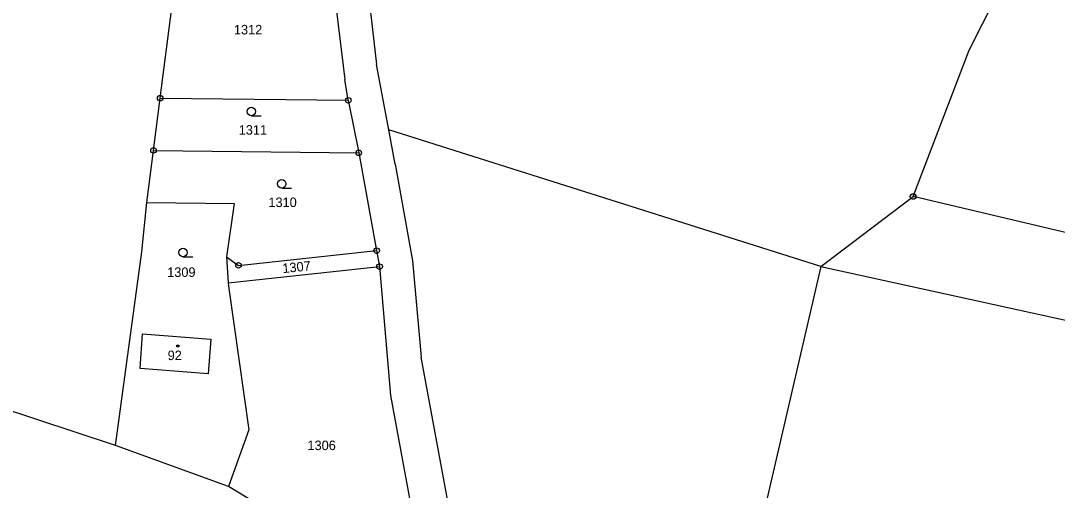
# Model space of a CAD drawing. Extents: x -796130 to -793145, y -1109506 to -1106267.
# Drawn here: x -794504.5 to -794319.4, y -1108047.8 to -1107964 of the extents above; entities that cross this region are included whole.
import ezdxf

# ---------------------------------------------------------------- set-up
doc = ezdxf.new("R2010")
doc.units = 0
for name, color, linetype in [('Vrstva 1', 7, 'Continuous'), ('Vrstva 14', 7, 'Continuous'), ('Vrstva 15', 7, 'Continuous'), ('Vrstva 23', 7, 'Continuous'), ('Vrstva 25', 7, 'Continuous'), ('Vrstva 28', 7, 'Continuous')]:
    doc.layers.add(name, color=color, linetype=linetype)

msp = doc.modelspace()

# ---------------------------------------------------------------- linework, layer by layer
at = {"layer": 'Vrstva 1'}
for p, q in [((-794479.59, -1107977.8), (-794474, -1107934.3)), ((-794335.13, -1107969.27), (-794328.35, -1107955.8)), ((-794448.48, -1107959.18), (-794446.64, -1107974.51)), ((-794442.46, -1107959.01), (-794440.99, -1107971.78)), ((-794345.16, -1107995.36), (-794335.13, -1107969.27)), ((-794438.78, -1107983.49), (-794440.99, -1107971.78)), ((-794446.02, -1107978.19), (-794446.64, -1107974.51)), ((-794480.79, -1107987.13), (-794479.59, -1107977.8)), ((-794479.59, -1107977.8), (-794446.02, -1107978.19)), ((-794446.02, -1107978.19), (-794444.15, -1107987.56)), ((-794437.63, -1107989.58), (-794438.78, -1107983.49)), ((-794361.62, -1108007.82), (-794438.78, -1107983.49)), ((-794481.98, -1107996.43), (-794480.79, -1107987.13)), ((-794480.79, -1107987.13), (-794444.15, -1107987.56)), ((-794444.15, -1107987.56), (-794440.95, -1108005.01)), ((-794437.63, -1107989.58), (-794434.53, -1108006.81)), ((-794482.9, -1108005.2), (-794481.98, -1107996.43)), ((-794481.98, -1107996.43), (-794466.39, -1107996.61)), ((-794466.39, -1107996.61), (-794467.74, -1108006.1)), ((-794361.62, -1108007.82), (-794345.16, -1107995.36)), ((-794271.47, -1108012.73), (-794345.16, -1107995.36)), ((-794487.55, -1108039.8), (-794482.9, -1108005.2)), ((-794465.62, -1108007.64), (-794440.95, -1108005.01)), ((-794440.95, -1108005.01), (-794440.43, -1108007.87)), ((-794467.74, -1108006.1), (-794465.62, -1108007.64)), ((-794467.74, -1108006.1), (-794467.48, -1108010.75)), ((-794467.48, -1108010.75), (-794440.43, -1108007.87)), ((-794440.43, -1108007.87), (-794438.45, -1108030.86)), ((-794434.53, -1108006.81), (-794433.02, -1108024.01)), ((-794361.62, -1108007.82), (-794389.73, -1108128.9)), ((-794361.62, -1108007.82), (-794306.61, -1108019.91)), ((-794487.55, -1108039.8), (-794584.35, -1108007.9)), ((-794467.48, -1108010.75), (-794467.34, -1108011.75)), ((-794467.34, -1108011.75), (-794463.76, -1108036.99)), ((-794483.19, -1108026.07), (-794482.73, -1108019.89)), ((-794482.73, -1108019.89), (-794470.58, -1108020.82)), ((-794470.58, -1108020.82), (-794471.03, -1108027)), ((-794425.07, -1108066.76), (-794433.02, -1108024.01)), ((-794471.03, -1108027), (-794483.19, -1108026.07)), ((-794438.45, -1108030.86), (-794434.88, -1108050.22)), ((-794463.76, -1108036.99), (-794467.4, -1108047.08)), ((-794467.4, -1108047.08), (-794487.55, -1108039.8)), ((-794445.93, -1108060.11), (-794467.4, -1108047.08))]:
    msp.add_line(p, q, dxfattribs=at)
at = {"layer": 'Vrstva 23'}
for p, q in [((-794463.32, -1107980.94), (-794461.57, -1107980.94)), ((-794457.9, -1107993.85), (-794456.15, -1107993.85)), ((-794475.53, -1108006.1), (-794473.78, -1108006.1))]:
    msp.add_line(p, q, dxfattribs=at)
for centre in [(-794463.32, -1107980.19), (-794457.9, -1107993.1), (-794475.53, -1108005.35)]:
    msp.add_circle(centre, 0.75, dxfattribs=at)
at = {"layer": 'Vrstva 25'}
for p, q in [((-794476.6, -1108021.86), (-794476.3, -1108021.86)), ((-794476.6, -1108022.16), (-794476.6, -1108021.86)), ((-794476.3, -1108022.16), (-794476.6, -1108022.16)), ((-794476.3, -1108021.86), (-794476.3, -1108022.16))]:
    msp.add_line(p, q, dxfattribs=at)
at = {"layer": 'Vrstva 28'}
for centre, radius in [((-794479.59, -1107977.8), 0.5), ((-794479.59, -1107977.8), 0.01), ((-794446.02, -1107978.19), 0.5), ((-794446.02, -1107978.19), 0.01), ((-794480.79, -1107987.13), 0.5), ((-794480.79, -1107987.13), 0.01), ((-794444.15, -1107987.56), 0.5), ((-794444.15, -1107987.56), 0.01), ((-794345.16, -1107995.36), 0.5), ((-794345.16, -1107995.36), 0.01), ((-794440.95, -1108005.01), 0.5), ((-794440.95, -1108005.01), 0.01), ((-794465.62, -1108007.64), 0.5), ((-794465.62, -1108007.64), 0.01), ((-794440.43, -1108007.87), 0.5), ((-794440.43, -1108007.87), 0.01)]:
    msp.add_circle(centre, radius, dxfattribs=at)

# ---------------------------------------------------------------- texts
at = {"layer": 'Vrstva 14'}
for s, p in [('1312', (-794466.433, -1107966.44)), ('1311', (-794465.576, -1107984.33)), ('1310', (-794460.272, -1107997.24)), ('1309', (-794478.349, -1108009.71)), ('1306', (-794453.299, -1108040.61))]:
    msp.add_text(s, height=1.7, dxfattribs=at).set_placement(p)
msp.add_text('1307', height=1.7, rotation=5.4, dxfattribs=at).set_placement((-794457.693, -1108009.027))
at = {"layer": 'Vrstva 15'}
msp.add_text('92', height=1.7, dxfattribs=at).set_placement((-794478.267, -1108024.55))

doc.saveas('drawing.dxf')
